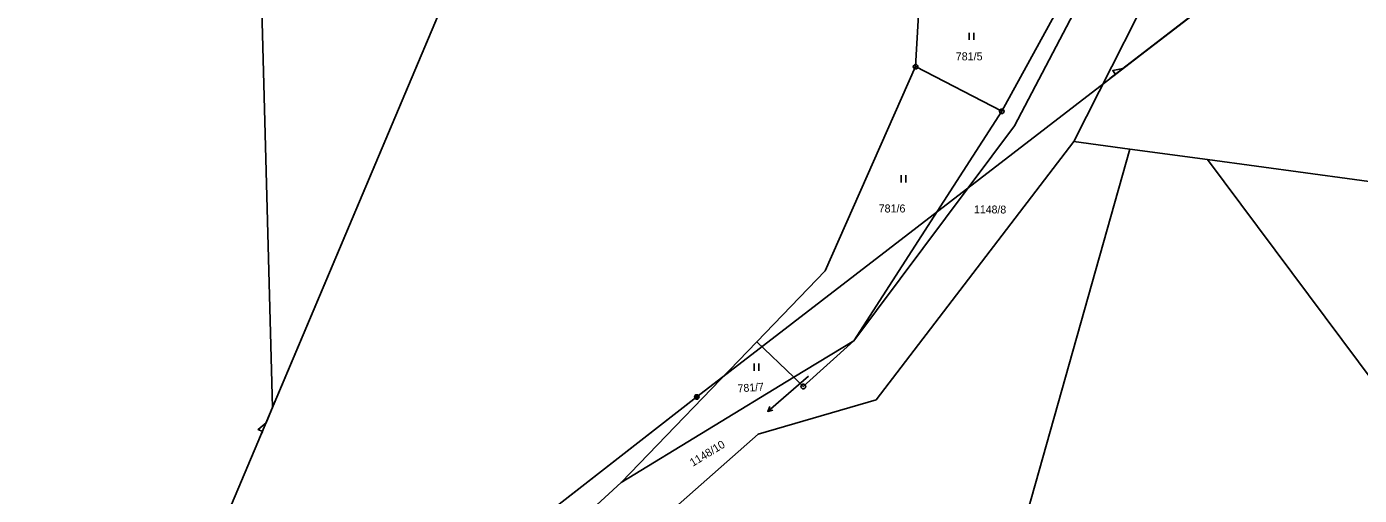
# Model space of a CAD drawing. Extents: x -747792 to -745414, y -1093712 to -1091463.
# Drawn here: x -746030.8 to -745889.3, y -1091740.4 to -1091690.6 of the extents above; entities that cross this region are included whole.
import ezdxf

# ---------------------------------------------------------------- set-up
doc = ezdxf.new("R2010")
doc.units = 0
for name, color, linetype in [('Budovy', 7, 'Continuous'), ('Doplňkové značky', 7, 'Continuous'), ('Doplňující texty', 7, 'Continuous'), ('Koleje_dopravní prvky', 7, 'Continuous'), ('Stromy_porost', 7, 'Continuous'), ('Značky IS', 7, 'Continuous')]:
    doc.layers.add(name, color=color, linetype=linetype)

msp = doc.modelspace()

# ---------------------------------------------------------------- linework, layer by layer
at = {"layer": 'Budovy'}
for points in [[(-745930.74, -1091691.25), (-745930.74, -1091692)], [(-745930.24, -1091692), (-745930.24, -1091691.25)], [(-745937.94, -1091706.38), (-745937.94, -1091707.13)], [(-745937.44, -1091707.13), (-745937.44, -1091706.38)], [(-745953.57, -1091726.39), (-745953.57, -1091727.14)], [(-745953.07, -1091727.14), (-745953.07, -1091726.39)]]:
    msp.add_lwpolyline(points, dxfattribs=at)
at = {"layer": 'Doplňkové značky'}
for points in [[(-745947.78, -1091727.73), (-745950.98, -1091730.49)], [(-745952.12, -1091731.47), (-745950.98, -1091730.49)], [(-745951.58, -1091731.33), (-745952.12, -1091731.47), (-745951.9, -1091730.95)]]:
    msp.add_lwpolyline(points, dxfattribs=at)
at = {"layer": 'Doplňující texty'}
for points in [[(-745936.33, -1091694.6), (-745936.21, -1091694.7), (-745936.16, -1091694.84), (-745936.21, -1091694.99), (-745936.33, -1091695.08), (-745936.49, -1091695.08), (-745936.61, -1091694.99), (-745936.66, -1091694.84), (-745936.61, -1091694.7), (-745936.49, -1091694.6)], [(-745927.2, -1091699.34), (-745927.07, -1091699.44), (-745927.02, -1091699.58), (-745927.07, -1091699.73), (-745927.2, -1091699.82), (-745927.34, -1091699.82), (-745927.47, -1091699.73), (-745927.52, -1091699.58), (-745927.47, -1091699.44), (-745927.34, -1091699.34)], [(-745948.26, -1091728.58), (-745948.14, -1091728.68), (-745948.09, -1091728.82), (-745948.14, -1091728.97), (-745948.26, -1091729.06), (-745948.42, -1091729.06), (-745948.54, -1091728.97), (-745948.59, -1091728.82), (-745948.54, -1091728.68), (-745948.42, -1091728.58)]]:
    msp.add_lwpolyline(points, close=True, dxfattribs=at)
for points in [[(-745936.44, -1091694.84), (-745936.39, -1091694.84)], [(-745927.3, -1091699.58), (-745927.24, -1091699.58)], [(-745948.36, -1091728.82), (-745948.32, -1091728.82)]]:
    msp.add_lwpolyline(points, dxfattribs=at)
at = {"layer": 'Stromy_porost'}
for points in [[(-745925.92, -1091701.12), (-745912.98, -1091676.47)], [(-745919.62, -1091702.79), (-745908.88, -1091681.58)], [(-745936.41, -1091694.84), (-745935.82, -1091684.4)], [(-745927.27, -1091699.58), (-745919.33, -1091685.08)], [(-745946.01, -1091716.54), (-745936.41, -1091694.84)], [(-745936.41, -1091694.84), (-745927.27, -1091699.58)], [(-745942.97, -1091723.95), (-745927.27, -1091699.58)], [(-745942.97, -1091723.95), (-745925.92, -1091701.12)], [(-745940.61, -1091730.24), (-745919.62, -1091702.79)], [(-745924.91, -1091743.52), (-745913.66, -1091703.59)], [(-745919.62, -1091702.79), (-745913.66, -1091703.59)], [(-745913.66, -1091703.59), (-745905.42, -1091704.71)], [(-745905.42, -1091704.71), (-745880.41, -1091738.2)], [(-745905.42, -1091704.71), (-745863.77, -1091710.37)], [(-745953.27, -1091724.06), (-745946.01, -1091716.54)], [(-745967.69, -1091739), (-745953.27, -1091724.06)], [(-745953.27, -1091724.06), (-745949.35, -1091727.84)], [(-745942.97, -1091723.95), (-745949.35, -1091727.84)], [(-745948.34, -1091728.82), (-745942.97, -1091723.95)], [(-745949.35, -1091727.84), (-745967.69, -1091739)], [(-745949.35, -1091727.84), (-745948.34, -1091728.82)], [(-745953.12, -1091733.88), (-745940.61, -1091730.24)], [(-746026.69, -1091798.86), (-745953.12, -1091733.88)], [(-746029.94, -1091796.18), (-745967.69, -1091739)]]:
    msp.add_lwpolyline(points, dxfattribs=at)
at = {"layer": 'Značky IS'}
for points in [[(-745913, -1091693.98), (-745803.42, -1091609.82), (-745859.6, -1091652.96)], [(-746004.72, -1091731.06), (-746007.25, -1091637.24), (-746005.94, -1091685.9)], [(-745959.66, -1091729.93), (-745869.11, -1091660.16), (-745915.77, -1091696.11)], [(-746026.14, -1091781.77), (-745984.67, -1091683.58), (-746006.09, -1091734.29)], [(-745915.57, -1091695.96), (-745915.18, -1091695.66), (-745915.48, -1091695.26), (-745914.39, -1091695.04), (-745913.2, -1091694.13)], [(-746095.38, -1091835.77), (-745959.66, -1091729.93), (-746028.9, -1091783.92)], [(-745959.74, -1091729.69), (-745959.58, -1091729.69), (-745959.46, -1091729.78), (-745959.41, -1091729.92), (-745959.46, -1091730.07), (-745959.58, -1091730.16), (-745959.74, -1091730.16), (-745959.86, -1091730.07), (-745959.91, -1091729.92), (-745959.86, -1091729.78), (-745959.74, -1091729.69), (-745959.72, -1091729.71), (-745959.6, -1091729.71), (-745959.52, -1091729.75), (-745959.8, -1091729.75), (-745959.84, -1091729.79), (-745959.48, -1091729.79), (-745959.48, -1091729.83), (-745959.84, -1091729.83), (-745959.86, -1091729.87), (-745959.46, -1091729.87), (-745959.44, -1091729.91), (-745959.88, -1091729.91), (-745959.88, -1091729.95), (-745959.44, -1091729.95), (-745959.46, -1091729.99), (-745959.86, -1091729.99), (-745959.85, -1091730.03), (-745959.45, -1091730.03), (-745959.48, -1091730.07), (-745959.83, -1091730.07), (-745959.8, -1091730.11), (-745959.52, -1091730.11), (-745959.57, -1091730.15), (-745959.74, -1091730.15)], [(-746005.99, -1091734.06), (-746005.79, -1091733.6), (-746006.25, -1091733.4), (-746005.41, -1091732.68), (-746004.82, -1091731.29)]]:
    msp.add_lwpolyline(points, dxfattribs=at)

# ---------------------------------------------------------------- texts
at = {"layer": 'Doplňkové značky'}
msp.add_text('1148/10', height=0.85, rotation=31.4554, dxfattribs=at).set_placement((-745960.07, -1091737.35))
at = {"layer": 'Koleje_dopravní prvky'}
for s, p in [('781/5', (-745932.15, -1091694.17)), ('781/6', (-745940.34, -1091710.33))]:
    msp.add_text(s, height=0.85, dxfattribs=at).set_placement(p)
for s, height, rotation, p in [('1148/8', 0.835, 359.4737, (-745930.21, -1091710.41)), ('1148/10', 0.05, 36.612, (-745947.85, -1091727.63)), ('781/7', 0.835, 3.9534, (-745955.29, -1091729.44))]:
    msp.add_text(s, height=height, rotation=rotation, dxfattribs=at).set_placement(p)

doc.saveas('drawing.dxf')
